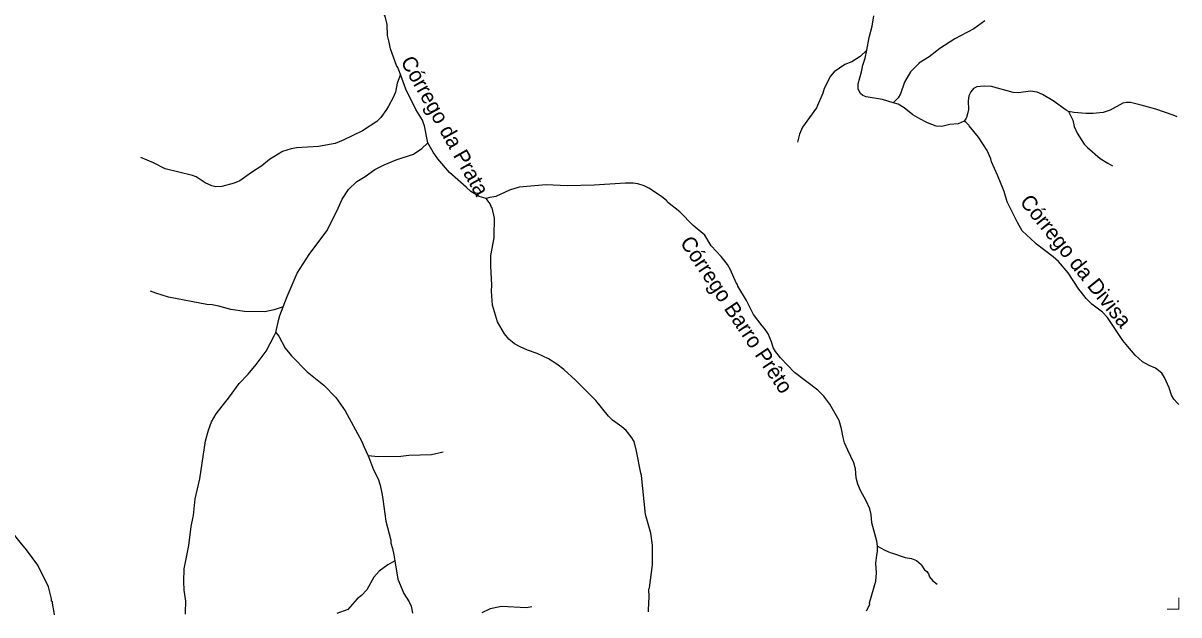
# Model space of a CAD drawing. Extents: x 396 to 422.2, y 7649.8 to 7677.6.
# Drawn here: x 416.1 to 422.18, y 7649.94 to 7653.05 of the extents above; entities that cross this region are included whole.
import ezdxf
from ezdxf.enums import TextEntityAlignment as Align

# ---------------------------------------------------------------- set-up
doc = ezdxf.new("R2010")
doc.units = 0
doc.header["$LTSCALE"] = 0.032
doc.layers.add('61', color=7, linetype='Continuous')
doc.layers.add('63', color=7, linetype='Continuous', lineweight=13)
doc.layers.add('7', color=7, linetype='Continuous', lineweight=25)

msp = doc.modelspace()

# ---------------------------------------------------------------- linework, layer by layer
at = {"layer": '63'}
msp.add_lwpolyline([(422.1134, 7649.9694), (422.175, 7649.9694), (422.175, 7650.0301)], dxfattribs=at)
at = {"layer": '7'}
for points in [[(418.0863, 7652.7787), (418.0732, 7652.8149), (418.0663, 7652.8259), (418.0341, 7652.9133), (418.0263, 7652.9485), (418.0185, 7652.9834), (418.017, 7653.0399), (418.0058, 7653.0839), (417.9268, 7653.218), (417.877, 7653.3465), (417.8226, 7653.4269), (417.805, 7653.4647), (417.797, 7653.5053), (417.7855, 7653.6384), (417.776, 7653.6843), (417.7627, 7653.7305), (417.7523, 7653.7949), (417.6797, 7653.9564), (417.6607, 7653.9853), (417.6456, 7654.0025), (417.6264, 7654.0156), (417.603, 7654.0244), (417.5863, 7654.0245), (417.5775, 7654.028)], [(420.5359, 7652.905), (420.5491, 7652.9717), (420.5639, 7653.0309), (420.5733, 7653.0858)], [(421.1561, 7653.0589), (421.0975, 7653.0184), (420.999, 7652.9649), (420.9201, 7652.9143), (420.8626, 7652.8715), (420.81, 7652.8372), (420.8083, 7652.8354), (420.7656, 7652.7914), (420.7344, 7652.7374), (420.713, 7652.6757), (420.7011, 7652.656), (420.6748, 7652.6295)], [(420.5359, 7652.905), (420.5017, 7652.8727), (420.4566, 7652.8447), (420.4199, 7652.8311), (420.3637, 7652.7921), (420.3444, 7652.769), (420.3122, 7652.7049), (420.3057, 7652.6791), (420.2708, 7652.6028), (420.1977, 7652.5014), (420.1816, 7652.4645), (420.1718, 7652.4232)], [(420.6748, 7652.6295), (420.618, 7652.6473), (420.532, 7652.6604), (420.5153, 7652.6676), (420.502, 7652.6784), (420.4908, 7652.701), (420.4908, 7652.7281), (420.5081, 7652.7916), (420.5146, 7652.8271), (420.5278, 7652.8642), (420.5359, 7652.905)], [(418.0863, 7652.7787), (418.07, 7652.732), (418.0599, 7652.6855), (418.0468, 7652.6529), (418.0229, 7652.6109), (418.0138, 7652.5949), (417.9836, 7652.5526), (417.9632, 7652.5312), (417.8868, 7652.4825), (417.7863, 7652.4329), (417.7433, 7652.4162), (417.6561, 7652.3999), (417.5413, 7652.3936), (417.5128, 7652.388), (417.4666, 7652.3728), (417.3993, 7652.3319), (417.3589, 7652.2987), (417.3047, 7652.2628), (417.2428, 7652.2187), (417.2127, 7652.2069), (417.1489, 7652.1894), (417.117, 7652.1879), (417.0949, 7652.1932), (417.0606, 7652.209), (417.0142, 7652.2396), (416.9949, 7652.2483), (416.8513, 7652.2826), (416.7892, 7652.314), (416.7226, 7652.3418)], [(418.2308, 7652.4184), (418.2132, 7652.5077), (418.2094, 7652.5175), (418.2017, 7652.5378), (418.1676, 7652.5946), (418.1143, 7652.7011), (418.0863, 7652.7787)], [(421.5953, 7652.5836), (421.5827, 7652.5904), (421.5145, 7652.6402), (421.4594, 7652.6729), (421.4314, 7652.6855), (421.3961, 7652.6895), (421.332, 7652.6824), (421.3038, 7652.6833), (421.1909, 7652.7142), (421.1519, 7652.7174), (421.114, 7652.7125), (421.0969, 7652.7045), (421.0814, 7652.6867), (421.0714, 7652.6652), (421.0682, 7652.6401), (421.0697, 7652.5943), (421.0651, 7652.5713), (421.0593, 7652.5514), (421.0576, 7652.5486), (421.0477, 7652.5321)], [(421.0477, 7652.5321), (421.016, 7652.5195), (420.9724, 7652.5148), (420.9297, 7652.5053), (420.901, 7652.5068), (420.8552, 7652.5239), (420.8137, 7652.5443), (420.7775, 7652.5668), (420.7325, 7652.603), (420.6999, 7652.6216), (420.6748, 7652.6295)], [(422.1667, 7652.556), (422.1456, 7652.5635), (422.0545, 7652.5959), (421.9776, 7652.6164), (421.9215, 7652.6313), (421.8991, 7652.6312), (421.881, 7652.6273), (421.8142, 7652.5904), (421.7767, 7652.5787), (421.7252, 7652.5738), (421.6869, 7652.5738), (421.6234, 7652.5786), (421.5953, 7652.5836)], [(422.1739, 7651.0448), (422.1681, 7651.0514), (422.1492, 7651.0727), (422.1361, 7651.0934), (422.124, 7651.1332), (422.0997, 7651.1869), (422.0859, 7651.209), (422.0516, 7651.236), (422.019, 7651.2491), (421.9847, 7651.2692), (421.9459, 7651.3045), (421.906, 7651.3492), (421.8812, 7651.3818), (421.7999, 7651.5023), (421.7734, 7651.5297), (421.7182, 7651.5711), (421.6883, 7651.6012), (421.6569, 7651.641), (421.6503, 7651.6508), (421.5934, 7651.7359), (421.5432, 7651.7957), (421.5154, 7651.8198), (421.4268, 7651.886), (421.4206, 7651.8944), (421.3519, 7651.9568), (421.327, 7652.0001), (421.306, 7652.0424), (421.2727, 7652.1094), (421.2578, 7652.1643), (421.2216, 7652.2485), (421.1912, 7652.3195), (421.1876, 7652.3349), (421.1672, 7652.3789), (421.1228, 7652.4488), (421.0736, 7652.5088), (421.0713, 7652.5116), (421.058, 7652.526), (421.0477, 7652.5321)], [(421.5953, 7652.5836), (421.608, 7652.5595), (421.6182, 7652.5374), (421.6253, 7652.5043), (421.6406, 7652.4704), (421.6771, 7652.4127), (421.6944, 7652.3942), (421.7613, 7652.3359), (421.802, 7652.3128), (421.8266, 7652.2988)], [(417.4703, 7651.5581), (417.4907, 7651.6128), (417.5442, 7651.7339), (417.6071, 7651.8324), (417.6998, 7651.9572), (417.752, 7652.0599), (417.7797, 7652.1234), (417.8127, 7652.1733), (417.8573, 7652.2165), (417.901, 7652.2414), (417.9526, 7652.2781), (418.0006, 7652.3033), (418.0644, 7652.3297), (418.1543, 7652.3595), (418.1981, 7652.3887), (418.2308, 7652.4184)], [(418.5373, 7652.1259), (418.4998, 7652.1372), (418.456, 7652.1639), (418.4312, 7652.1859), (418.3443, 7652.2632), (418.2822, 7652.3349), (418.2585, 7652.3698), (418.2308, 7652.4184)], [(420.5919, 7650.3017), (420.5878, 7650.3263), (420.5626, 7650.4235), (420.5592, 7650.4676), (420.5519, 7650.4963), (420.5331, 7650.5383), (420.5028, 7650.594), (420.4894, 7650.6272), (420.4803, 7650.6602), (420.4763, 7650.7077), (420.4669, 7650.7393), (420.437, 7650.8051), (420.4192, 7650.8441), (420.4119, 7650.8707), (420.403, 7650.917), (420.3901, 7650.96), (420.3414, 7651.0461), (420.3093, 7651.0886), (420.2781, 7651.1193), (420.1553, 7651.2131), (420.0828, 7651.2893), (420.0562, 7651.3239), (420.044, 7651.3445), (420.036, 7651.3731), (420.017, 7651.4159), (419.9994, 7651.4446), (419.9857, 7651.4588), (419.9408, 7651.5179), (419.9046, 7651.5914), (419.8585, 7651.6664), (419.8574, 7651.6758), (419.85, 7651.6845), (419.8191, 7651.7527), (419.8034, 7651.7808), (419.7783, 7651.8141), (419.771, 7651.8219), (419.7179, 7651.8788), (419.6852, 7651.9334), (419.6244, 7651.9856), (419.5531, 7652.0568), (419.4895, 7652.108), (419.4858, 7652.1144), (419.4577, 7652.1378), (419.3914, 7652.1816), (419.3672, 7652.1929), (419.3334, 7652.2037), (419.3079, 7652.207), (419.2677, 7652.207), (419.1038, 7652.1959), (418.9618, 7652.1927), (418.8521, 7652.1991), (418.7107, 7652.1854), (418.6593, 7652.1702), (418.587, 7652.1371), (418.5566, 7652.1327), (418.5373, 7652.1259)], [(419.3894, 7649.9556), (419.3898, 7649.9662), (419.3923, 7650.0348), (419.3902, 7650.0754), (419.3942, 7650.0815), (419.4109, 7650.203), (419.4109, 7650.3061), (419.4013, 7650.3695), (419.3743, 7650.4665), (419.3518, 7650.6717), (419.3492, 7650.6845), (419.3263, 7650.799), (419.3133, 7650.8503), (419.299, 7650.8754), (419.2711, 7650.9089), (419.2488, 7650.9282), (419.1995, 7650.9621), (419.1783, 7650.9834), (419.1124, 7651.0659), (419.0292, 7651.1501), (419.0051, 7651.1724), (418.9441, 7651.2287), (418.9083, 7651.2567), (418.8634, 7651.2842), (418.8051, 7651.3129), (418.7544, 7651.3295), (418.7146, 7651.347), (418.6863, 7651.3643), (418.6556, 7651.3888), (418.633, 7651.4153), (418.5955, 7651.4793), (418.5704, 7651.5671), (418.5649, 7651.6398), (418.5663, 7651.6707), (418.5607, 7651.7715), (418.5609, 7651.8268), (418.5791, 7651.9196), (418.5792, 7651.9291), (418.5799, 7652.0226), (418.5689, 7652.0773), (418.5651, 7652.0788), (418.5573, 7652.0988), (418.5373, 7652.1259)], [(417.4703, 7651.5581), (417.4227, 7651.542), (417.3738, 7651.5315), (417.2681, 7651.5332), (417.1948, 7651.5431), (417.1329, 7651.5619), (417.0968, 7651.5684), (417.0691, 7651.5699), (416.8682, 7651.6089), (416.8013, 7651.6288), (416.7737, 7651.64)], [(417.4319, 7651.4228), (417.4485, 7651.4928), (417.453, 7651.5116), (417.4703, 7651.5581)], [(416.9581, 7649.9435), (416.9582, 7649.9522), (416.9586, 7650.0126), (416.9506, 7650.0701), (416.9482, 7650.1159), (416.95, 7650.1811), (416.9745, 7650.3038), (416.9866, 7650.405), (416.9978, 7650.4555), (416.9992, 7650.462), (417.0089, 7650.5486), (417.0334, 7650.6543), (417.0623, 7650.8532), (417.0777, 7650.9109), (417.0948, 7650.9546), (417.1189, 7650.9964), (417.1884, 7651.0852), (417.2391, 7651.1556), (417.2865, 7651.2037), (417.3289, 7651.2543), (417.3804, 7651.3251), (417.4239, 7651.405), (417.4319, 7651.4228)], [(417.4319, 7651.4228), (417.4481, 7651.4033), (417.4814, 7651.3403), (417.5139, 7651.3008), (417.5963, 7651.2171), (417.6846, 7651.1469), (417.7474, 7651.0822), (417.7961, 7651.012), (417.882, 7650.8547), (417.8952, 7650.8212), (417.917, 7650.7752)], [(418.3112, 7650.7939), (418.2502, 7650.7804), (418.1298, 7650.777), (418.0878, 7650.7724), (417.9701, 7650.7692), (417.917, 7650.7752)], [(417.917, 7650.7752), (417.929, 7650.7443), (417.9453, 7650.701), (417.9689, 7650.6537), (417.9795, 7650.6212), (417.9899, 7650.5698), (417.9944, 7650.5473), (418.009, 7650.4314), (418.0359, 7650.332), (418.0361, 7650.3166), (418.0451, 7650.2881), (418.0517, 7650.2554), (418.0569, 7650.2242)], [(416.2701, 7649.94), (416.2679, 7649.9531), (416.2597, 7650.0012), (416.2584, 7650.0088), (416.2545, 7650.0127), (416.2543, 7650.0241), (416.2375, 7650.0875), (416.1814, 7650.2015), (416.1225, 7650.2812), (416.0888, 7650.3225), (415.958, 7650.4826), (415.8534, 7650.5742), (415.8149, 7650.5989), (415.754, 7650.6302), (415.7081, 7650.6429), (415.5756, 7650.6875), (415.4004, 7650.7388), (415.3669, 7650.7527)], [(420.5349, 7649.9612), (420.5367, 7649.9647), (420.552, 7649.994), (420.5504, 7650.0038), (420.5828, 7650.1166), (420.5872, 7650.1608), (420.5833, 7650.2108), (420.5889, 7650.2544), (420.5912, 7650.2723), (420.5919, 7650.3017)], [(420.5919, 7650.3017), (420.6298, 7650.2793), (420.6305, 7650.279), (420.6579, 7650.2675), (420.6705, 7650.2635), (420.7376, 7650.242), (420.7706, 7650.2369), (420.7976, 7650.226), (420.8206, 7650.2038), (420.8238, 7650.2008), (420.8388, 7650.1764), (420.851, 7650.1671), (420.8595, 7650.1563), (420.8656, 7650.14), (420.8805, 7650.1202), (420.9047, 7650.1009)], [(418.0569, 7650.2242), (418.0204, 7650.2021), (417.9753, 7650.1699), (417.9468, 7650.1386), (417.9102, 7650.0716), (417.8813, 7650.041), (417.8588, 7650.0239), (417.81, 7649.9675), (417.7525, 7649.9475)], [(418.0569, 7650.2242), (418.073, 7650.128), (418.1043, 7650.0528), (418.1317, 7650.0091), (418.1427, 7649.9854), (418.1499, 7649.9495)], [(418.777, 7649.9828), (418.749, 7649.9765), (418.6163, 7649.9843), (418.5585, 7649.9722), (418.5145, 7649.9513)]]:
    msp.add_lwpolyline(points, dxfattribs=at)

# ---------------------------------------------------------------- texts
at = {"layer": '61'}
for s, rotation, p in [('Córrego da Prata', 299.283, (418.2856, 7652.4893)), ('Córrego da Divisa', 308.747, (421.6033, 7651.7738)), ('Córrego Barro Prêto', 303.69, (419.8191, 7651.4949))]:
    msp.add_text(s, height=0.08, rotation=rotation, dxfattribs=at).set_placement(p, align=Align.CENTER)

doc.saveas('drawing.dxf')
